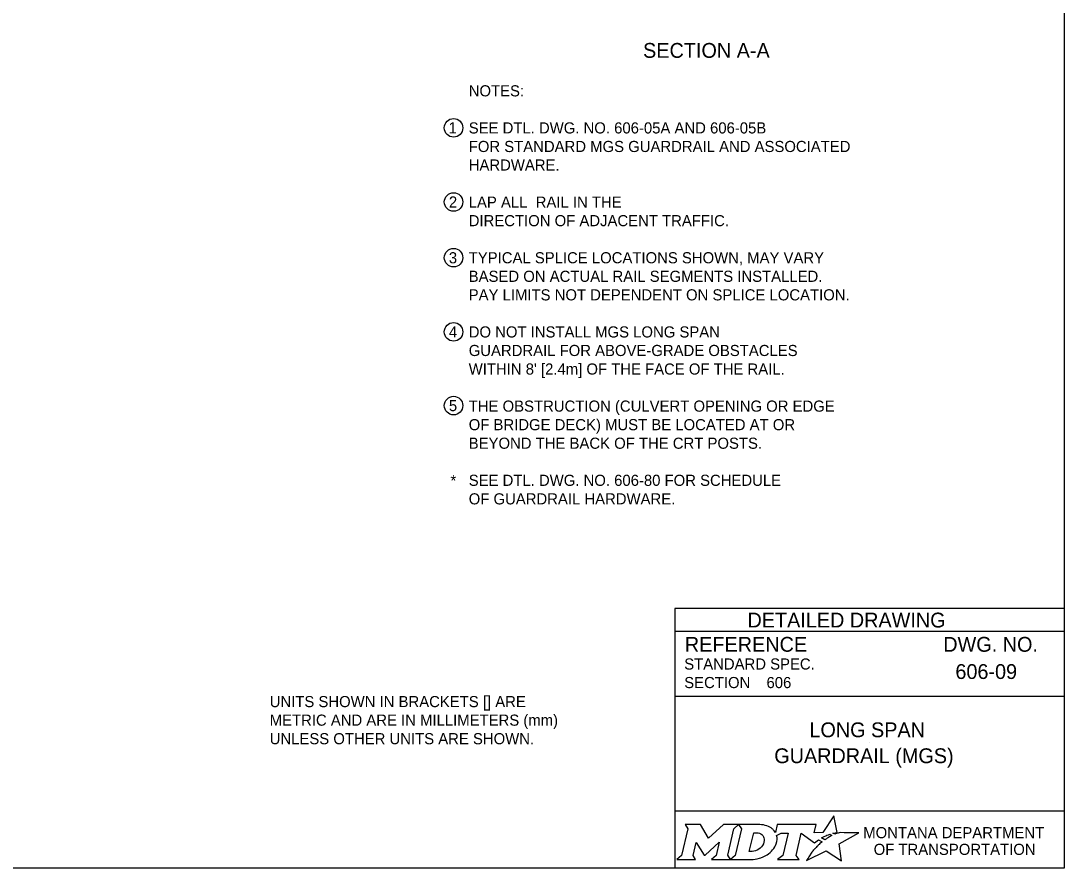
# Model space of a CAD drawing. Extents: x 49991.4 to 50021, y 49987.6 to 50011.4.
# Drawn here: x 50011.12 to 50016.75, y 49987.8 to 49992.37 of the extents above; entities that cross this region are included whole.
import ezdxf

# ---------------------------------------------------------------- set-up
doc = ezdxf.new("R2010")
doc.units = 0
for name, color, linetype in [('Default', 7, 'Continuous'), ('Level 1', 7, 'Continuous'), ('Level 2', 7, 'Continuous'), ('Level 5', 7, 'Continuous')]:
    doc.layers.add(name, color=color, linetype=linetype)

msp = doc.modelspace()

# ---------------------------------------------------------------- linework, layer by layer
at = {"layer": 'Default'}
for points in [[(50015.5126, 49987.9811), (50015.5023, 49987.9867), (50015.5139, 49987.9895), (50015.5255, 49987.9915), (50015.5081, 49988.0816), (50015.4486, 49987.9903), (50015.4013, 49987.9896), (50015.4116, 49988.0337), (50015.2024, 49988.0338), (50015.1923, 49987.9913), (50015.1865, 49987.9996)], [(50014.7056, 49988.0338), (50014.7197, 49988.0104), (50014.6862, 49987.8671), (50014.6605, 49987.8446), (50014.7621, 49987.8446), (50014.7486, 49987.8674), (50014.7648, 49987.9375), (50014.8085, 49987.8685), (50014.8138, 49987.8685), (50014.8889, 49987.938), (50014.8725, 49987.8669), (50014.8478, 49987.8449), (50014.9494, 49987.8449), (50014.9356, 49987.8682), (50014.9688, 49988.0106)], [(50014.9688, 49988.0106), (50014.9941, 49988.0338), (50014.9117, 49988.0338), (50014.8321, 49987.9608), (50014.7876, 49988.0335), (50014.7056, 49988.0338)], [(50015.1077, 49988.0338), (50014.9941, 49988.0338), (50015.0088, 49988.0109), (50014.9749, 49987.8671), (50014.9494, 49987.8449), (50015.06, 49987.8449)], [(50015.1317, 49987.9471), (50015.1305, 49987.939), (50015.1273, 49987.9297), (50015.1231, 49987.9215), (50015.1175, 49987.914), (50015.111, 49987.9071), (50015.1031, 49987.9008), (50015.0948, 49987.8961), (50015.0857, 49987.8922), (50015.0766, 49987.8899), (50015.0674, 49987.889), (50015.0515, 49987.889), (50015.0751, 49987.989), (50015.0911, 49987.989), (50015.0987, 49987.9884), (50015.1063, 49987.9865), (50015.1129, 49987.9835), (50015.119, 49987.9793), (50015.1238, 49987.9743), (50015.1275, 49987.9683), (50015.1302, 49987.9621), (50015.1318, 49987.9547), (50015.1318, 49987.9517), (50015.1317, 49987.9471)], [(50015.1991, 49987.9747), (50015.2237, 49987.9878), (50015.2606, 49987.9878), (50015.232, 49987.8673), (50015.2045, 49987.8446), (50015.3207, 49987.8446), (50015.3037, 49987.8675), (50015.3319, 49987.9877), (50015.4032, 49987.936), (50015.4243, 49987.9511), (50015.444, 49987.9402)], [(50015.3882, 49987.8843), (50015.3729, 49987.8599), (50015.3682, 49987.8524), (50015.3624, 49987.8438), (50015.3601, 49987.8395), (50015.4654, 49987.8926), (50015.5493, 49987.8375), (50015.5362, 49987.9302), (50015.6431, 49987.9886), (50015.5938, 49987.9894), (50015.5637, 49987.9898), (50015.5429, 49987.9901), (50015.5361, 49987.9886), (50015.5312, 49987.9874), (50015.5228, 49987.9851), (50015.5126, 49987.9811)], [(50015.4622, 49987.9535), (50015.4598, 49987.9518), (50015.4415, 49987.9614), (50015.4518, 49987.9671), (50015.4559, 49987.9693), (50015.4645, 49987.9733), (50015.4702, 49987.9759), (50015.4781, 49987.9789), (50015.4854, 49987.9816), (50015.4972, 49987.9742), (50015.4932, 49987.9721), (50015.4886, 49987.9696), (50015.4844, 49987.9674), (50015.4794, 49987.9645), (50015.4775, 49987.9634), (50015.4748, 49987.9618), (50015.4723, 49987.9604), (50015.47, 49987.9588), (50015.4674, 49987.957), (50015.4647, 49987.9552), (50015.4622, 49987.9535)], [(50015.4021, 49987.9004), (50015.4021, 49987.9004)], [(50015.1057, 49987.8522), (50015.1141, 49987.8548), (50015.1271, 49987.8602), (50015.1475, 49987.8712)]]:
    msp.add_lwpolyline(points, dxfattribs=at)
for centre, radius, start, end in [((50015.1308, 49987.9554), 0.0709, 339.5329, 15.8582), ((50015.0868, 49987.9727), 0.1183, 300.9103, 339.1383)]:
    msp.add_arc(centre, radius, start, end, dxfattribs=at)
for centre, major_axis, ratio, start_param, end_param in [((50015.1056, 49987.9864), (0.0834, -0.0037), 0.568097, 0.61298, 1.570796), ((50015.1612, 49987.9937), (0.0361, -0.0295), 0.469099, 1.225588, 1.570796), ((50015.3952, 49987.8923), (-0.00694, -0.00806), 0.008222, 0, 3.137361), ((50015.4119, 49987.9106), (-0.0098, -0.0102), 0.016458, 3.141593, 6.279097), ((50015.4329, 49987.9305), (-0.0112, -0.0097), 0.021651, 3.157348, 6.283185), ((50015.0603, 49987.9932), (0, 0.1484), 0.987302, 3.139398, 3.456847)]:
    msp.add_ellipse(centre, major_axis=major_axis, ratio=ratio, start_param=start_param, end_param=end_param, dxfattribs=at)
at = {"layer": 'Level 1'}
msp.add_lwpolyline([(49999.3835, 49998.9992), (50016.7501, 49998.9992), (50016.7501, 49987.7988), (49999.3835, 49987.7988)], close=True, dxfattribs=at)
at = {"layer": 'Level 2'}
for centre in [(50013.456, 49991.7901), (50013.456, 49991.3904), (50013.456, 49991.0901), (50013.456, 49990.6901), (50013.456, 49990.2927)]:
    msp.add_circle(centre, 0.05, dxfattribs=at)
at = {"layer": 'Level 5'}
for p, q in [((50016.7501, 49989.1988), (50014.6501, 49989.1988)), ((50014.6501, 49989.1988), (50014.6501, 49987.7988)), ((50016.7501, 49989.0738), (50014.6501, 49989.0738)), ((50016.3862, 49988.8587), (50016.3862, 49988.8587)), ((50015.1444, 49988.7993), (50015.1444, 49988.7993)), ((50016.7501, 49988.7238), (50014.6501, 49988.7238)), ((50015.7001, 49988.4747), (50015.7001, 49988.4747)), ((50016.7501, 49988.1057), (50014.6501, 49988.1057))]:
    msp.add_line(p, q, dxfattribs=at)

# ---------------------------------------------------------------- texts
at = {"layer": 'Default'}
for s, p in [('MONTANA DEPARTMENT', (50015.6663, 49987.96)), ('OF TRANSPORTATION', (50015.7225, 49987.87))]:
    msp.add_text(s, height=0.06, dxfattribs=at).set_placement(p)
at = {"layer": 'Level 2'}
for s, height, p in [('SECTION A-A', 0.08, (50014.4783, 49992.1677)), ('NOTES:', 0.06, (50013.5377, 49991.9598)), ('1', 0.06, (50013.4285, 49991.7601)), ('SEE DTL. DWG. NO. 606-05A AND 606-05B ', 0.06, (50013.5377, 49991.7598)), ('FOR STANDARD MGS GUARDRAIL AND ASSOCIATED ', 0.06, (50013.5377, 49991.6598)), ('HARDWARE.', 0.06, (50013.5377, 49991.5598)), ('2', 0.06, (50013.4308, 49991.3604)), ('LAP ALL  RAIL IN THE', 0.06, (50013.5377, 49991.3598)), ('DIRECTION OF ADJACENT TRAFFIC.', 0.06, (50013.5377, 49991.2598)), ('3', 0.06, (50013.4306, 49991.0598)), ('TYPICAL SPLICE LOCATIONS SHOWN, MAY VARY', 0.06, (50013.5377, 49991.0598)), ('BASED ON ACTUAL RAIL SEGMENTS INSTALLED.', 0.06, (50013.5377, 49990.9598)), ('PAY LIMITS NOT DEPENDENT ON SPLICE LOCATION.', 0.06, (50013.5377, 49990.8598)), ('4', 0.06, (50013.4308, 49990.6599)), ('DO NOT INSTALL MGS LONG SPAN ', 0.06, (50013.5377, 49990.6598)), ('GUARDRAIL FOR ABOVE-GRADE OBSTACLES ', 0.06, (50013.5377, 49990.5598)), ("WITHIN 8' [2.4m] OF THE FACE OF THE RAIL.", 0.06, (50013.5377, 49990.4598)), ('5', 0.06, (50013.4308, 49990.2625)), ('THE OBSTRUCTION (CULVERT OPENING OR EDGE ', 0.06, (50013.5377, 49990.2598)), ('OF BRIDGE DECK) MUST BE LOCATED AT OR', 0.06, (50013.5377, 49990.1598)), ('BEYOND THE BACK OF THE CRT POSTS.', 0.06, (50013.5377, 49990.0598)), ('*', 0.06, (50013.4391, 49989.8585)), ('SEE DTL. DWG. NO. 606-80 FOR SCHEDULE', 0.06, (50013.5377, 49989.8598)), ('OF GUARDRAIL HARDWARE.', 0.06, (50013.5377, 49989.7598)), ('606-09', 0.0799, (50016.1635, 49988.8187)), ('606', 0.06, (50015.1444, 49988.7693)), ('UNITS SHOWN IN BRACKETS [] ARE ', 0.06, (50012.4639, 49988.6667)), ('METRIC AND ARE IN MILLIMETERS (mm) ', 0.06, (50012.4639, 49988.5667)), ('LONG SPAN', 0.0799, (50015.3758, 49988.5046)), ('UNLESS OTHER UNITS ARE SHOWN.', 0.06, (50012.4639, 49988.4667)), ('GUARDRAIL (MGS)', 0.0799, (50015.1862, 49988.3647))]:
    msp.add_text(s, height=height, dxfattribs=at).set_placement(p)
at = {"layer": 'Level 5'}
for s, height, p in [('DETAILED DRAWING', 0.0799, (50015.0418, 49989.0963)), ('REFERENCE', 0.08, (50014.7037, 49988.9654)), ('DWG. NO.', 0.08, (50016.0979, 49988.9654)), ('STANDARD SPEC.', 0.06, (50014.7004, 49988.8694)), ('SECTION', 0.06, (50014.7004, 49988.7694))]:
    msp.add_text(s, height=height, dxfattribs=at).set_placement(p)

doc.saveas('drawing.dxf')
